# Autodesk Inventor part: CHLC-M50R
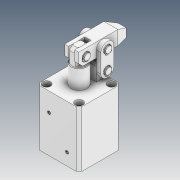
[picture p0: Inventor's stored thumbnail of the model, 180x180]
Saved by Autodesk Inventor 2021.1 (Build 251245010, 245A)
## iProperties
Created: 2019-11
Part Number: CHLC-M50R
Material: Ogólny
Description: STEP AP214
Document SubType Name: Modeling
Designer: user
Density: 1 g/cm^3
Appearance: Domyślna
Company: Microsoft
Title: chlc-m50_asm-R.STEP
Author: Windows
Revision Number: ÈÎºÎ
Sending System: SolidWorks 2015
Preprocessor: SwSTEP 2.0
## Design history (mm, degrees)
feature "CHLC-50-06-5-solid1"
feature "CHLC-50-04-1-solid1"
feature "CHLC-50-03-2-solid1"
feature "CHLC-50-02-1-solid1"
feature "M6LS_1-2-solid1"
feature "CHLC-50-06-3-solid1"
feature "CHLC-50-06-1-solid1"
feature "CHLC-50£­Í¹Ì¨-1-solid1"
feature "CHLC-50-06-6-solid1"
feature "CHLC-50-04-2-solid1"
feature "CHLC-50-06-4-solid1"
feature "CHLC-50-09-1-solid1"
feature "CHLC-50-06-2-solid1"
feature "M6LS_1-1-solid1"
feature "CHLC-50-01-1-solid1"
feature "CHLC-50-03-1-solid1"
feature "Í¹Ì¨-À­Éì1"
node "Bryła1"
node "Bryła2"
node "Bryła3"
node "Bryła4"
node "Bryła5"
node "Bryła6"
node "Bryła7"
node "Bryła8"
node "Bryła9"
node "Bryła10"
node "Bryła11"
node "Bryła12"
node "Bryła13"
node "Bryła14"
node "Bryła15"
node "Bryła16"
node "Bryła17"
